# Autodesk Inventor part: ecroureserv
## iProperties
Shininess: 86.0
Length Units: 11269
Angle Units: 11279
Time Units: 11290
Mass Units: 11283
Length Display Precision: 3
Angle Display Precision: 2
Compacted: True
Created: 2001-12
Part Number: ecroureserv
Material: Par défaut
Document SubType Name: Modélisation
Designer: pichon
Density: 0.0
Volumn: 0.0
Area: 0.0
PropertySet Name: Model Information
Control State: 0
Master: False
Checked Out: False
Author: pichon
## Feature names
1. Extrusion1
2. Révolution1 [Revolution]
3. Révolution2 [Revolution]
4. Révolution3 [Revolution]
5. Révolution4 [Revolution]
6. Chanfrein1 [Chamfer]
7. Extrusion2
8. Réseau circulaire1 [Circular Pattern]
